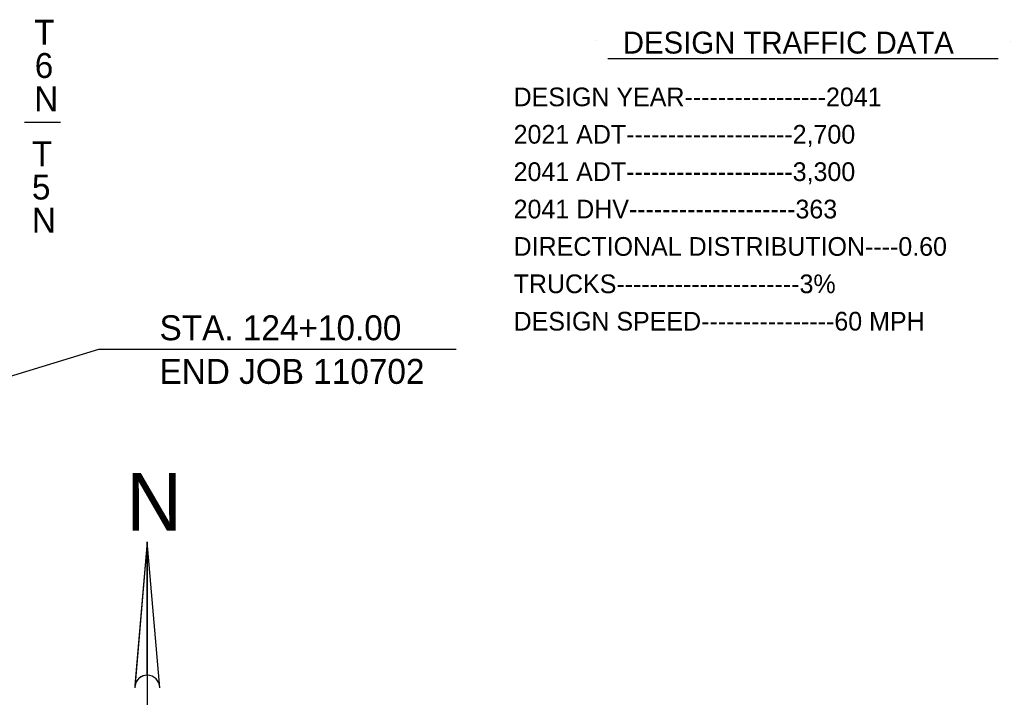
# Model space of a CAD drawing. Extents: x 155 to 3386, y 68 to 2138.
# Drawn here: x 2346 to 3141, y 761 to 1304 of the extents above; entities that cross this region are included whole.
import ezdxf

# ---------------------------------------------------------------- set-up
doc = ezdxf.new("R2010")
doc.units = 0
doc.layers.add('2', color=7, linetype='Continuous')
doc.layers.add('R_Draft', color=7, linetype='Continuous')

msp = doc.modelspace()

# ---------------------------------------------------------------- linework, layer by layer
at = {"layer": '2'}
for p, q in [((2807.86, 1287.54), (2807.86, 1287.54)), ((3140.52, 1287.17), (3140.52, 1287.17)), ((2817.65, 1273.19), (3130.74, 1273.19)), ((2378.51, 1221.89), (2349.57, 1221.89)), ((1718.72, 829.66), (2409.24, 1039.86)), ((2409.24, 1039.86), (2696.04, 1039.86))]:
    msp.add_line(p, q, dxfattribs=at)
at = {"layer": 'R_Draft'}
for p, q in [((2448.14, 885.31), (2438.28, 770)), ((2448.14, 885.31), (2448.14, 727.4)), ((2448.14, 778.31), (2448.14, 885.31)), ((2438.42, 771.61), (2438.87, 772.06)), ((2438.47, 772.23), (2439.38, 773.14))]:
    msp.add_line(p, q, dxfattribs=at)
msp.add_lwpolyline([(2458.14, 768.31), (2448.14, 885.31), (2438.14, 768.31)], dxfattribs=at)
for start, end in [(0, 180), (90, 170.22959)]:
    msp.add_arc((2448.14, 768.31), 10, start, end, dxfattribs=at)

# ---------------------------------------------------------------- texts
at = {"layer": '2'}
for s, height, p in [('T', 20, (2357.38, 1284.29)), ('DESIGN TRAFFIC DATA', 17.6113, (2829.68, 1277.19)), ('6', 20, (2357.86, 1257.62)), ('N', 20, (2357.38, 1230.95)), ('DESIGN YEAR-----------------2041', 15, (2742.08, 1234.91)), ('2021 ADT--------------------2,700', 15, (2742.08, 1204.91)), ('T', 20, (2355.57, 1186.74)), ('2041 ADT--------------------3,300', 15, (2742.08, 1174.91)), ('5', 20, (2355.57, 1160.07)), ('N', 20, (2355.57, 1133.4)), ('2041 DHV--------------------363', 15, (2742.08, 1144.91)), ('DIRECTIONAL DISTRIBUTION----0.60', 15, (2742.08, 1114.91)), ('TRUCKS----------------------3%', 15, (2742.08, 1084.91)), ('STA. 124+10.00', 20, (2457.97, 1047.13)), ('DESIGN SPEED----------------60 MPH', 15, (2742.08, 1054.91)), ('END JOB 110702', 20, (2457.97, 1012.13))]:
    msp.add_text(s, height=height, dxfattribs=at).set_placement(p)
at = {"layer": 'R_Draft'}
msp.add_text('N', height=46.15, dxfattribs=at).set_placement((2431.27, 894.39))

doc.saveas('drawing.dxf')
